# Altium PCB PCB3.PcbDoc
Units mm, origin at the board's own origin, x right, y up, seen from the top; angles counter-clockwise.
Board outline 81 x 21 mm, 2 copper layers (Top Layer, Bottom Layer); 12 components, 0 nets, 46 pads, 0 vias.
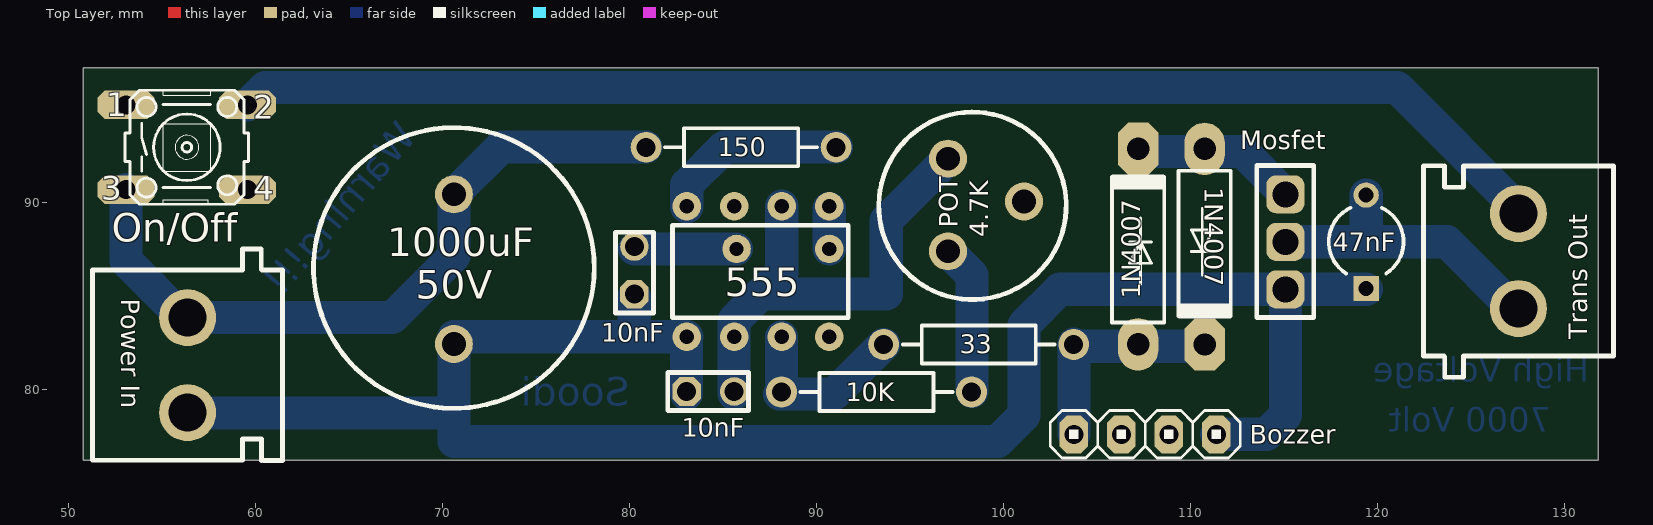
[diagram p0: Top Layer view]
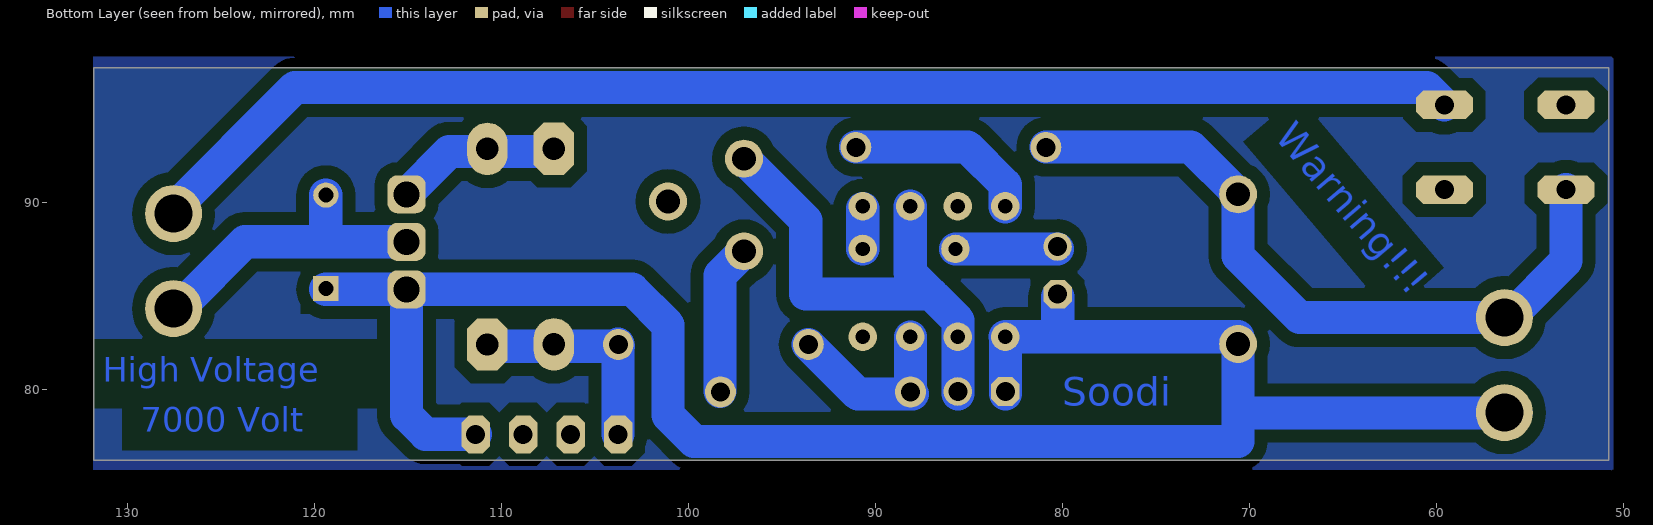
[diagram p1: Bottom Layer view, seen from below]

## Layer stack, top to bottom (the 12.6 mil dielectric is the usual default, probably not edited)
Top Layer: signal copper 0.0356
Dielectric: dielectric 0.32, FR-4, Dk 4.8
Bottom Layer: signal copper 0.0356

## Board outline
50.8,76.2 131.8,76.2 131.8,97.2 50.8,97.2

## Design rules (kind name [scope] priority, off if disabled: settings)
Clearance Clearance_Poly [All vs InPoly] p1: gap=0.7
Clearance [All] p2: gap=0.2
PolygonConnect [All] p1: connectstyle=Relief reliefconductorwidth=0.254 reliefentries=4 polygonreliefangle="90 Angle"
RoutingVias [All] p1: holewidth=0.6 width=1 viastyle="Through Hole" minholewidth=0.711 minwidth=1.27 maxholewidth=0.711 maxwidth=1.27
SilkscreenOverComponentPads [All] p1: minsilkscreentomaskgap=0.254
SolderMaskExpansion [All] p1: expansion=0.102
Width [All] p1: maxlimit=0.2 minlimit=0.2 preferedwidth=0.2
27 further rules are at their usual default settings.

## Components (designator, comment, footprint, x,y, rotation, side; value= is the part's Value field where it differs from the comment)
? "Comment" My_cap100n 84.328,79.883 r0 top
? "Comment" My_axial-0.4 85.979,92.951 r0 top
? "Comment" My_cap100n 80.264,86.36 r90 top
? "Comment" My_axial-0.4 93.218,79.87 r0 top
? "Comment" My_axial-0.4 98.679,82.41 r0 top
? "Comment" My_DO-41 106.934,93.091 r270 top
? "Comment" My_DO-41 110.998,82.169 r90 top
? "Comment" My_CN2 61.468,86.36 r270 top
? "Comment" MY_TACTILE-PTH 56.388,92.964 r0 top
? "Comment" My_CN2 122.428,81.788 r90 top
? "Comment" My_1X04 107.569,77.597 r0 top
? "Comment" CAPR5-4X5 119.38,87.884 r90 top

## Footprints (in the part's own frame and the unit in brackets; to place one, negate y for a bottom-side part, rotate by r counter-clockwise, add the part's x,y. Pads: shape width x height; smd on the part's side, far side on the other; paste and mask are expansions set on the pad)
CAPR5-4X5 [mm] "Capacitor; 2 Leads"
  rect 1.35x1.35 hole 0.8: 1(-2.5,0)
  round 1.35 hole 0.8: 2(2.5,0)
  silkscreen extent -1.69,-2 1.82,2
My_1X04 [mil]
  oct 60x80 hole 40: 1(-150,0) 2(-50,0) 3(50,0) 4(150,0)
  silkscreen extent -200,-50 200,50
My_axial-0.4 [mil]
  round 65 hole 40: 1(-200.5,-0.5) 2(199.5,-0.5)
  silkscreen extent -160,-40 160,40
My_cap100n [mil]
  oct 60x60 hole 40: 1(-50,0)
  round 60 hole 40: 2(50,0)
  silkscreen extent -90,-40 80,40
My_CN2 [mil]
  round 120 hole 80: 1(99.5,-200.5) 2(299.5,-200.5)
  silkscreen extent -45,-400 400,0
My_DO-41 [mil]
  oval 110x85 hole 47.24: A(420.71,10)
  oct 110x85 hole 47.24: K(8.9,10)
  silkscreen extent 64,-45 375,65
MY_TACTILE-PTH [mil]
  oct 120x60 hole 40: 1(-130,88) 1(126,88) 2(-130,-90) 2(126,-90)
  silkscreen extent -132,-121 128,119

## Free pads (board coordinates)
  round 2.032 hole 1.27: 0(70.612,90.424) 1(70.612,82.423) 13(97.028,87.376) 14(97.028,92.329) 15(101.092,90.043)
  rrect50% 2.032x2.032 hole 1.397: 0(115.062,85.344) 0(115.062,87.884) 0(115.062,90.424)
  round 1.524 hole 0.762: 2(83.058,82.804) 2(83.058,89.789) 2(88.138,82.804) 2(88.138,89.789) 3(85.598,82.804) 3(85.598,89.789) 3(90.678,82.804) 3(90.678,89.789) 4(90.678,87.503) 5(85.725,87.503)

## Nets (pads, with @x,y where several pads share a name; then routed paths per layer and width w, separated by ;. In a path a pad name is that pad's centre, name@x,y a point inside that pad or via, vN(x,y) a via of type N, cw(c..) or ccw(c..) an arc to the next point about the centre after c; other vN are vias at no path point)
pads on no net: ?.1 ?.2 ?.3 ?.4 ?.A ?.K
copper on no net: | length 312.3
  Bottom Layer w1.778: 53.086,90.678 53.086,86.868 56.121,83.833 67.323,83.833 70.612,87.122 70.612,90.424 73.139,92.951 80.886,92.951 ; 55.753,78.74 70.612,78.74 ; 59.588,95.199 60.528,96.139 121.031,96.139 127.648,89.522 ; 80.251,82.804 80.251,84.95 ; 80.264,87.503 85.725,87.503 ; 83.045,79.756 83.045,82.791 ; 83.058,82.804 70.612,82.804 70.612,77.216 99.695,77.216 101.092,78.613 101.092,83.439 102.997,85.344 115.062,85.344 115.062,78.613 114.046,77.597 111.379,77.597 ; 83.058,89.764 83.058,90.932 85.077,92.951 91.046,92.951 ; 85.585,79.756 85.585,83.68 88.138,86.233 88.138,89.789 ; 86.995,85.09 93.726,85.09 93.726,89.027 97.028,92.329 ; 88.024,79.743 90.932,79.743 93.586,82.398 ; 88.125,79.756 88.125,82.791 ; 90.678,87.503 90.678,89.662 ; 97.028,87.376 98.311,86.093 98.311,79.896 ; 103.746,82.296 110.744,82.296 ; 103.759,77.597 103.759,82.423 ; 107.061,92.71 112.776,92.71 115.062,90.424 ; 114.935,85.344 119.38,85.344 ; 115.062,87.884 123.698,87.884 127.127,84.455 ; 119.38,87.884 119.38,90.384

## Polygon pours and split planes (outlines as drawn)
no net on Bottom Layer "Bottom Layer-No Net" (solid, pour order 1000): 131.826,97.79 50.673,97.79 50.546,97.663 50.546,75.565 50.673,75.692 131.826,75.692

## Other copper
Bottom Layer:
  text "Warning!!!" at 68.707,93.472 h1.52 r49.59
  text "High Voltage" at 131.318,80.391 h1.3
  text "Soodi" at 80.01,79.121 h1.52
  text "7000 Volt" at 129.286,77.724 h1.3

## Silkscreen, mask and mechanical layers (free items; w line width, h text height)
Top Overlay:
  circle w0.254: c70.612,86.486 r7.503
  lines w0.254: 100.763,85.427 cw(c98.335,89.81) 100.806,85.45 ; 113.525,91.834 113.525,83.833 116.573,83.833 116.573,91.961 113.525,91.961 ; 82.296,83.82 91.694,83.82 91.694,88.773 82.296,88.773 82.296,83.82
  text "Mosfet" at 112.649,92.837 h1
  text "150" at 84.709,92.456 h1
  text "1N4007" at 110.744,90.805 h1 r270
  text "POT" at 97.536,88.646 h1 r90
  text "4.7K" at 99.187,88.138 h1 r90
  text "On/Off" at 52.324,87.884 h1.52
  text "47nF" at 117.602,87.376 h1
  text "1000uF" at 67.056,87.122 h1.52
  text "555" at 85.09,84.963 h1.52
  text "Power In" at 52.832,84.836 h1 r270
  text "50V" at 68.58,84.836 h1.52
  text "1N4007" at 107.315,84.836 h1 r90
  text "Trans Out" at 131.191,82.677 h1 r90
  text "10nF" at 78.486,82.55 h1
  text "33" at 97.663,81.915 h1
  text "10K" at 91.567,79.375 h1
  text "10nF" at 82.804,77.47 h1
  text "Bozzer" at 113.157,77.089 h1

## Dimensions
131.318,97.917 to 130.175,75.565 on Top Layer
50.8,76.2 to 131.826,86.106 on Top Layer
